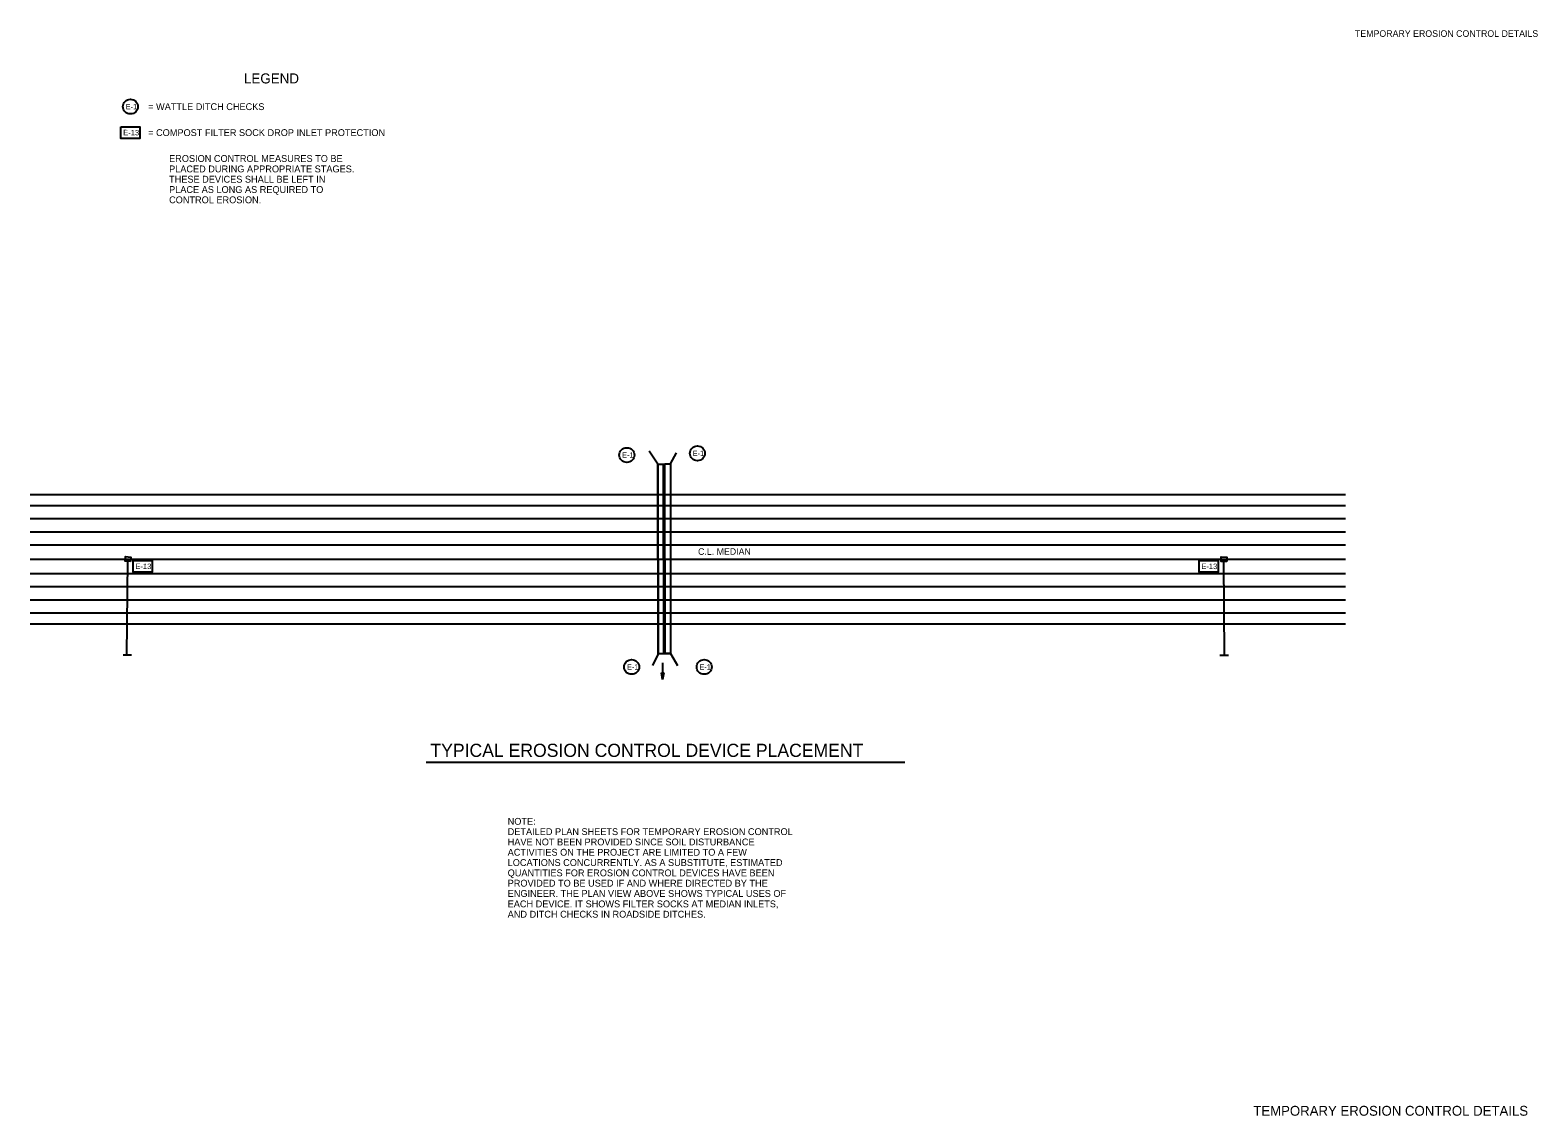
# Model space of a CAD drawing. Extents: x 1405295 to 1406670, y 2087573 to 2090763.
# Drawn here: x 1405295 to 1406670, y 2089773 to 2090763 of the extents above; entities that cross this region are included whole.
import ezdxf

# ---------------------------------------------------------------- set-up
doc = ezdxf.new("R2010")
doc.units = 0
for name, color, linetype in [('1', 7, 'Continuous'), ('43', 7, 'Continuous'), ('G-ANNO-TEXT', 7, 'Continuous'), ('G-No Plot-Stamp-2', 7, 'Continuous'), ('Level 1', 7, 'Continuous'), ('Level 44', 7, 'Continuous'), ('R_Draft', 7, 'Continuous'), ('R_No Plot', 7, 'Continuous'), ('R_Striping', 7, 'Continuous'), ('S_CROSS_DRAIN', 7, 'Continuous'), ('S_HEADWALL', 7, 'Continuous')]:
    doc.layers.add(name, color=color, linetype=linetype)

msp = doc.modelspace()

# ---------------------------------------------------------------- linework, layer by layer
at = {"layer": '1'}
for points in [[(1405377.4, 2090674.9), (1405394.7, 2090674.9), (1405394.7, 2090664.4), (1405377.4, 2090664.4)], [(1405388.5, 2090279.3), (1405405.8, 2090279.3), (1405405.8, 2090268.8), (1405388.5, 2090268.8)], [(1406361, 2090279.3), (1406378.4, 2090279.3), (1406378.4, 2090268.8), (1406361, 2090268.8)]]:
    msp.add_lwpolyline(points, close=True, dxfattribs=at)
at = {"layer": '43'}
for p, q in [((1405871.5, 2090170.7), (1405870.4, 2090176.8)), ((1405870.4, 2090176.8), (1405872.6, 2090176.8)), ((1405872.6, 2090176.8), (1405871.5, 2090170.7))]:
    msp.add_line(p, q, dxfattribs=at)
msp.add_lwpolyline([(1405871.5, 2090185.9), (1405871.5, 2090170.7)], dxfattribs=at)
at = {"layer": 'G-No Plot-Stamp-2'}
msp.add_line((1405294.5, 2090280.6), (1406494.5, 2090280.6), dxfattribs=at)
at = {"layer": 'Level 1'}
msp.add_line((1405655.7, 2090095.4), (1406092.5, 2090095.4), dxfattribs=at)
for centre in [(1405386, 2090693.4), (1405838.9, 2090375.5), (1405903.3, 2090377.1), (1405843.3, 2090182.3), (1405909.5, 2090182.3)]:
    msp.add_ellipse(centre, major_axis=(-6.88, 0), ratio=0.97521, dxfattribs=at)
at = {"layer": 'R_No Plot'}
for p, q in [((1405294.5, 2090339.6), (1406494.5, 2090339.6)), ((1405294.5, 2090221.6), (1406494.5, 2090221.6))]:
    msp.add_line(p, q, dxfattribs=at)
at = {"layer": 'R_Striping'}
for p, q in [((1405294.5, 2090329.6), (1406494.5, 2090329.6)), ((1405294.5, 2090317.6), (1406494.5, 2090317.6)), ((1405294.5, 2090305.6), (1406494.5, 2090305.6)), ((1405294.5, 2090293.6), (1406494.5, 2090293.6)), ((1405294.5, 2090267.6), (1406494.5, 2090267.6)), ((1405294.5, 2090255.6), (1406494.5, 2090255.6)), ((1405294.5, 2090243.6), (1406494.5, 2090243.6)), ((1405294.5, 2090231.6), (1406494.5, 2090231.6))]:
    msp.add_line(p, q, dxfattribs=at)
at = {"layer": 'S_CROSS_DRAIN'}
for p, q in [((1405867.2, 2090367.3), (1405867.4, 2090194.3)), ((1405383.3, 2090279), (1405382.5, 2090193)), ((1406383.3, 2090278.7), (1406383.9, 2090192.7))]:
    msp.add_line(p, q, dxfattribs=at)
for points in [[(1405867.2, 2090367.3), (1405872.2, 2090367.3), (1405872.4, 2090194.3), (1405867.4, 2090194.3)], [(1405873.6, 2090367.4), (1405878.6, 2090367.4), (1405878.8, 2090194.4), (1405873.8, 2090194.4)], [(1405386.1, 2090278.3), (1405381.1, 2090278.7), (1405381.4, 2090282.9), (1405386.4, 2090282.5)], [(1406386.2, 2090278.3), (1406381.2, 2090278.3), (1406381.2, 2090282.6), (1406386.2, 2090282.5)]]:
    msp.add_lwpolyline(points, close=True, dxfattribs=at)
at = {"layer": 'S_HEADWALL'}
for p, q in [((1405867.2, 2090367.3), (1405859.4, 2090379.2)), ((1405878.6, 2090367.4), (1405884.1, 2090377.7)), ((1405867.2, 2090367.3), (1405878.6, 2090367.4)), ((1405867.4, 2090194.3), (1405862.2, 2090183.7)), ((1405867.4, 2090194.3), (1405878.8, 2090194.4)), ((1405878.8, 2090194.4), (1405885, 2090183.6)), ((1405387, 2090193), (1405379.3, 2090193)), ((1406387.8, 2090192.8), (1406380, 2090192.7))]:
    msp.add_line(p, q, dxfattribs=at)

# ---------------------------------------------------------------- texts
at = {"layer": '1'}
for p in [(1405379.4, 2090667.2), (1405390.5, 2090271.6), (1406363, 2090271.6)]:
    msp.add_text('E-13', height=5, rotation=359.6177, dxfattribs=at).set_placement(p)
at = {"layer": 'G-ANNO-TEXT'}
for height, p in [(6, (1406503.2, 2090757)), (9, (1406410.4, 2089772.9))]:
    msp.add_text('TEMPORARY EROSION CONTROL DETAILS', height=height, dxfattribs=at).set_placement(p)
at = {"layer": 'Level 1'}
for s, height, rotation, p in [('E-1', 4.88, 0, (1405381.7, 2090690.9)), ('= WATTLE DITCH CHECKS', 6.25, 0, (1405402.2, 2090690.2)), ('= COMPOST FILTER SOCK DROP INLET PROTECTION', 6.25, 0, (1405402.2, 2090666.5)), ('EROSION CONTROL MEASURES TO BE', 6.25, 0, (1405421.3, 2090642.9)), ('PLACED DURING APPROPRIATE STAGES. ', 6.25, 0, (1405421.3, 2090633.4)), ('THESE DEVICES SHALL BE LEFT IN', 6.25, 0, (1405421.3, 2090624)), ('PLACE AS LONG AS REQUIRED TO', 6.25, 0, (1405421.3, 2090614.6)), ('CONTROL EROSION.', 6.25, 0, (1405421.3, 2090605.2)), ('E-1', 4.88, 0, (1405834.6, 2090373.1)), ('E-1', 4.88, 0, (1405899, 2090374.7)), ('E-1', 4.88, 0, (1405839, 2090179.8)), ('E-1', 4.88, 0, (1405905.1, 2090179.8)), ('TYPICAL EROSION CONTROL DEVICE PLACEMENT', 12, 360, (1405659.7, 2090100.2))]:
    msp.add_text(s, height=height, rotation=rotation, dxfattribs=at).set_placement(p)
for s, p in [('NOTE:', (1405730.2, 2090038.3)), ('DETAILED PLAN SHEETS FOR TEMPORARY EROSION CONTROL', (1405730.2, 2090028.9)), ('ACTIVITIES ON THE PROJECT ARE LIMITED TO A FEW', (1405730.2, 2090010.1)), ('HAVE NOT BEEN PROVIDED SINCE SOIL DISTURBANCE', (1405730.2, 2090019.5)), ('LOCATIONS CONCURRENTLY. AS A SUBSTITUTE, ESTIMATED', (1405730.2, 2090000.7)), ('QUANTITIES FOR EROSION CONTROL DEVICES HAVE BEEN', (1405730.2, 2089991.3)), ('PROVIDED TO BE USED IF AND WHERE DIRECTED BY THE', (1405730.2, 2089981.9)), ('ENGINEER. THE PLAN VIEW ABOVE SHOWS TYPICAL USES OF', (1405730.2, 2089972.5)), ('AND DITCH CHECKS IN ROADSIDE DITCHES.', (1405730.2, 2089953.6)), ('EACH DEVICE. IT SHOWS FILTER SOCKS AT MEDIAN INLETS,', (1405730.2, 2089963))]:
    msp.add_text(s, height=6.25, dxfattribs=at).set_placement(p)
at = {"layer": 'Level 44'}
msp.add_text('LEGEND', height=9.14, rotation=0, dxfattribs=at).set_placement((1405489.6, 2090714.5))
at = {"layer": 'R_Draft'}
msp.add_text('C.L. MEDIAN', height=6, rotation=0.0557, dxfattribs=at).set_placement((1405903.9, 2090284.5))

doc.saveas('drawing.dxf')
